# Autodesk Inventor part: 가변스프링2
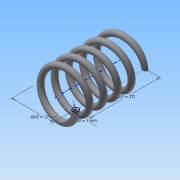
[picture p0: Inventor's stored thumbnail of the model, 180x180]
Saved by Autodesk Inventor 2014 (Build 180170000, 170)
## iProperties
Created: 2015-09
Part Number: 가변스프링2
Material: 강철, 탄소
Document SubType Name: Modeling
Designer: study
Density: 1 g/cm^3
Appearance: 반연마
Mass: 2.40066 g
Surface Area: 32.5308 cm^2
Volume: 2.40066 cm^3
Author: study
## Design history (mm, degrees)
sketch "스케치1"
  geometry: L1 (0, 0)-(11, 0); L2 (11, 0)-(11, 37); L3 (11, 37)-(0, 37); L4 (0, 37)-(0, 0); C1 r 1.5 at (11, 0)
  constraints: 8 end point, 2 parallel, 1 centre point, 1 coincident, 1 horizontal, 1 perpendicular
  dimensions: "d0" = 3 diameter of C1; "d2" = 22 diameter of L2 L4; "d3" = 37 distance of L1.end L2.end (derived)
feature "코일1" sketch "스케치1" pitch "d4" = 10; turns "d6" = 5; dims "d5" = 37 (= d3), "d7" = 0, angle "d8" = 90 deg, angle "d9" = 90 deg, "d10" = 0, "d11" = 0
node "작업 평면1"
sketch "스케치2"
  geometry: L1 (-12.5, 0)-(-9.5, 0) reference; 1 further point
  constraints: 1 horizontal alignment
extrude "돌출1" cut sketch "스케치2" stored distance "d13" = 10; taper "d14" = 0 deg
node "작업 평면2"
sketch "스케치3"
  geometry: L1 (-9.5, 0)-(-12.5, 0) reference; 1 further point
  constraints: 1 horizontal alignment
extrude "돌출2" cut sketch "스케치3" stored distance "d16" = 10; taper "d17" = 0 deg
node "솔리드1"
node "절단 모서리 투영1"
node "절단 모서리 투영2"
other parameters: "d12" = 0, "d15" = 37 (= d3)
